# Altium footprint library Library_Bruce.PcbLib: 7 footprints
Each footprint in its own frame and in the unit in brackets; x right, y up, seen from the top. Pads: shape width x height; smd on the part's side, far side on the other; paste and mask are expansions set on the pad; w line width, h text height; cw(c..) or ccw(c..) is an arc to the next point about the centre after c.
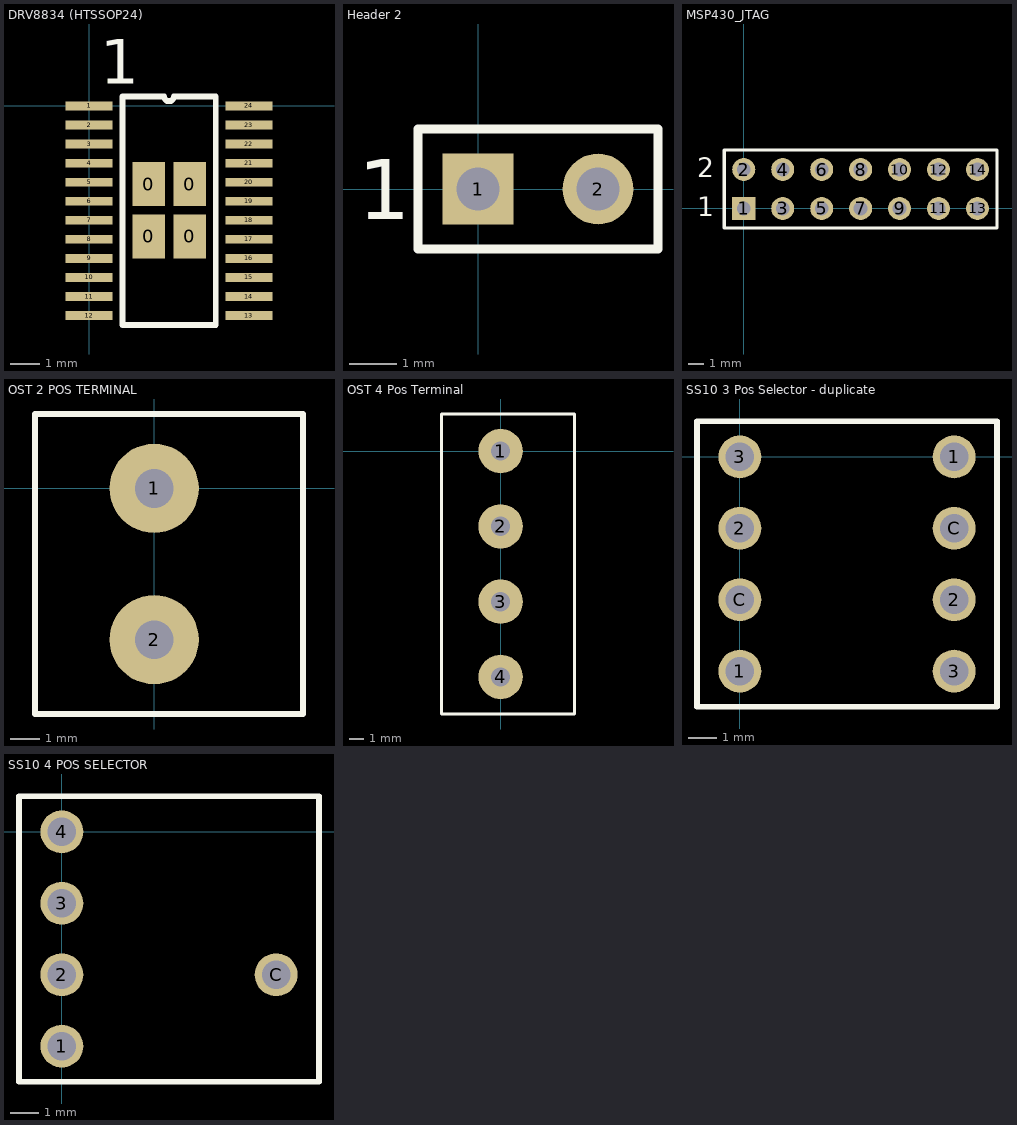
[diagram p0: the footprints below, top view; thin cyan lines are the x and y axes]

## DRV8834 (HTSSOP24) [mm]
pads (28):
  rect 1.1x1.5 smd: 0(2.032,-4.445) 0(2.032,-2.667) 0(3.429,-4.445) 0(3.429,-2.667)
  rect 1.6x0.3 smd mask+0.07: 1(0,0) 2(0,-0.65) 3(0,-1.3) 4(0,-1.95) 5(0,-2.6) 6(0,-3.25) 7(0,-3.9) 8(0,-4.55) 9(0,-5.2) 10(0,-5.85) 11(0,-6.5) 12(0,-7.15) 13(5.45,-7.15) 14(5.45,-6.5) 15(5.45,-5.85) 16(5.45,-5.2) 17(5.45,-4.55) 18(5.45,-3.9) 19(5.45,-3.25) 20(5.45,-2.6) 21(5.45,-1.95) 22(5.45,-1.3) 23(5.45,-0.65) 24(5.45,0)
Top Overlay:
  lines w0.2: 1.143,-7.475 4.318,-7.475 4.318,0.325 2.887,0.325 cw(c2.725,0.325) 2.562,0.325 1.143,0.325 1.143,-7.475
  text "1" at 0.381,0.762 h1.52

## Header 2 [mm]
pads (2):
  rect 1.5x1.5 hole 0.9: 1(0,0)
  round 1.5 hole 0.9: 2(2.54,0)
Top Overlay:
  lines w0.2: -1.27,-1.27 -1.27,1.27 3.81,1.27 3.81,-1.27 2.667,-1.27 -1.27,-1.27
  text "1" at -2.54,-0.635 h1.27

## MSP430_JTAG [mm] "Connector; Header; 7x2 Position"
pads (14):
  rect 1.5x1.5 hole 0.9: 1(0,0)
  round 1.5 hole 0.9: 2(0,2.54) 3(2.54,0) 4(2.54,2.54) 5(5.08,0) 6(5.08,2.54) 7(7.62,0) 8(7.62,2.54) 9(10.16,0) 10(10.16,2.54) 11(12.7,0) 12(12.7,2.54) 13(15.24,0) 14(15.24,2.54)
Top Overlay:
  lines w0.2: -1.27,-1.27 16.51,-1.27 16.51,3.81 -1.27,3.81 -1.27,-1.27
  text "1" at -3.048,-0.508 h1.27
  text "2" at -3.048,2.032 h1.27

## OST 2 POS TERMINAL [mm]
pads (2):
  round 3 hole 1.3 mask+0.254: 1(0,0) 2(0,-5.08)
Top Overlay:
  lines w0.2: -4,-7.58 5,-7.58 5,2.5 -4,2.5 -4,-7.58

## OST 4 Pos Terminal [mm]
pads (4):
  round 3 hole 1.3 mask+0.254: 1(0,0) 2(0,-5.08) 3(0,-10.16) 4(0,-15.24)
Top Overlay:
  lines w0.2: -4,-17.74 5,-17.74 5,2.5 -4,2.5 -4,-17.74

## SS10 3 Pos Selector - duplicate [mil]
pads (8):
  round 60 hole 40: 1(0,-300) 1(300,0) 2(0,-100) 2(300,-200) 3(0,0) 3(300,-300) C(0,-200) C(300,-100)
Top Overlay:
  lines w7.87: -45,-350 360,-350 360,50 175,50 -60,50 -60,-350 345,-350

## SS10 4 POS SELECTOR [mil]
pads (5):
  round 60 hole 40: 1(0,-300) 2(0,-200) 3(0,-100) 4(0,0) C(300,-200)
Top Overlay:
  lines w7.87: -45,-350 360,-350 360,50 175,50 -60,50 -60,-350 345,-350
